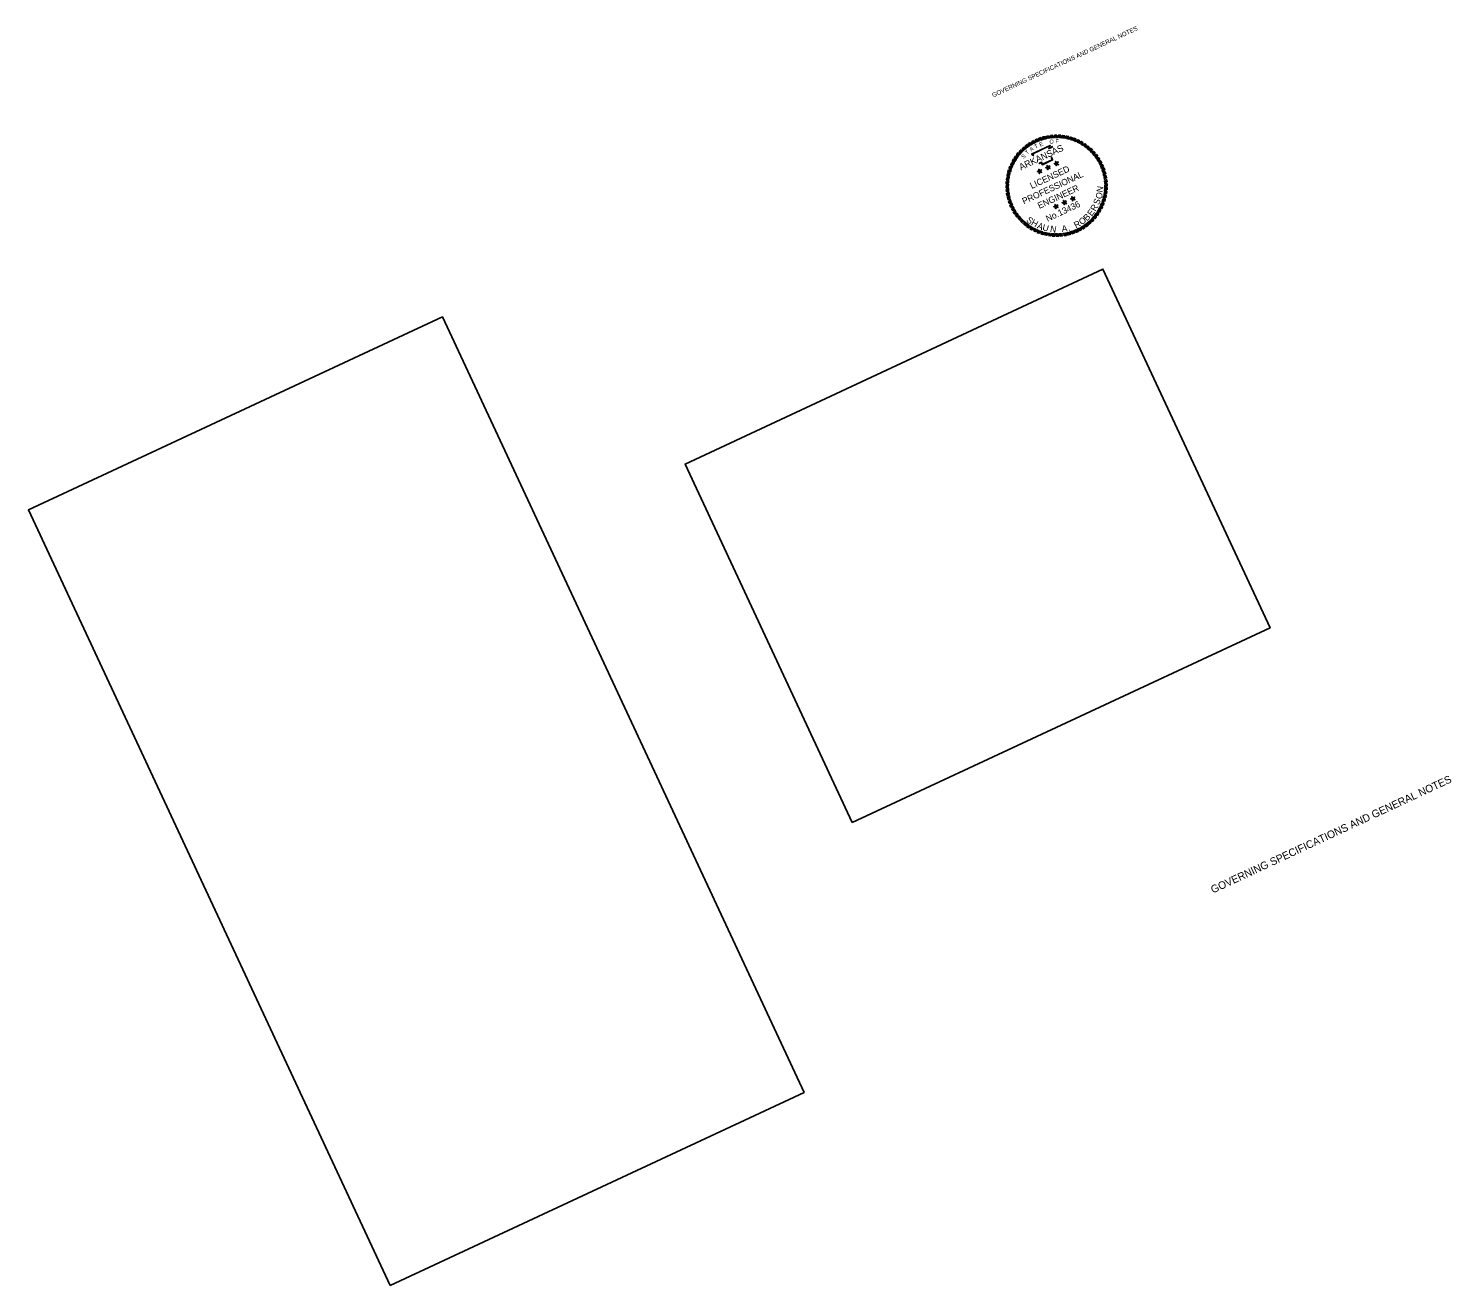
# Model space of a CAD drawing. Extents: x 757035 to 763666, y 1656342 to 1660766.
# Drawn here: x 760309 to 763666, y 1657801 to 1660766 of the extents above; entities that cross this region are included whole.
import ezdxf

# ---------------------------------------------------------------- set-up
doc = ezdxf.new("R2010")
doc.units = 0
for name, color, linetype in [('1', 7, 'Continuous'), ('60', 7, 'Continuous'), ('G-ANNO-SYMB', 7, 'Continuous')]:
    doc.layers.add(name, color=color, linetype=linetype)

msp = doc.modelspace()

# ---------------------------------------------------------------- linework, layer by layer
at = {"layer": '1'}
for points in [[(762252.5, 1658893), (763238.4, 1659352.7), (762844, 1660198.5), (761858.1, 1659738.8)], [(761162.2, 1657801), (762139, 1658256.5), (761285.8, 1660086.1), (760309, 1659630.7)]]:
    msp.add_lwpolyline(points, close=True, dxfattribs=at)
at = {"layer": 'G-ANNO-SYMB'}
for points in [[(762698.5, 1660509), (762693.7, 1660507.3), (762688.9, 1660499.5), (762694, 1660501.6)], [(762707.6, 1660511.5), (762702.6, 1660510.2), (762697.2, 1660502.8), (762702.5, 1660504.5)], [(762716.8, 1660513.2), (762711.7, 1660512.4), (762705.8, 1660505.4), (762711.2, 1660506.7)], [(762726.1, 1660514.3), (762721, 1660513.8), (762714.5, 1660507.3), (762720, 1660508.2)], [(762735.4, 1660514.6), (762730.3, 1660514.5), (762723.4, 1660508.6), (762728.9, 1660509)], [(762744.8, 1660514.2), (762739.7, 1660514.5), (762732.3, 1660509.1), (762737.8, 1660509.1)], [(762754.1, 1660513), (762749, 1660513.7), (762741.2, 1660509), (762746.7, 1660508.5)], [(762763.3, 1660511.1), (762758.3, 1660512.2), (762750.1, 1660508.1), (762755.6, 1660507.2)], [(762772.3, 1660508.5), (762767.4, 1660510), (762758.9, 1660506.5), (762764.3, 1660505.2)], [(762781, 1660505.2), (762776.3, 1660507.1), (762767.6, 1660504.3), (762772.8, 1660502.6)], [(762644.4, 1660473.3), (762641.2, 1660469.4), (762641.2, 1660460.2), (762644.4, 1660464.7)], [(762650.9, 1660480.2), (762647.3, 1660476.5), (762646.6, 1660467.4), (762650.2, 1660471.6)], [(762657.8, 1660486.5), (762653.9, 1660483.1), (762652.5, 1660474.1), (762656.4, 1660478)], [(762665.2, 1660492.2), (762661.1, 1660489.2), (762658.9, 1660480.3), (762663.2, 1660483.9)], [(762673, 1660497.4), (762668.7, 1660494.7), (762665.8, 1660486), (762670.3, 1660489.2)], [(762681.2, 1660501.9), (762676.7, 1660499.5), (762673.2, 1660491.1), (762677.9, 1660494)], [(762689.7, 1660505.8), (762685, 1660503.8), (762680.9, 1660495.6), (762685.8, 1660498.1)], [(762789.5, 1660501.2), (762784.9, 1660503.5), (762776, 1660501.4), (762781.1, 1660499.2)], [(762797.7, 1660496.6), (762793.3, 1660499.2), (762784.2, 1660497.8), (762789.2, 1660495.3)], [(762805.4, 1660491.4), (762801.2, 1660494.3), (762792.1, 1660493.6), (762796.8, 1660490.7)], [(762812.7, 1660485.5), (762808.8, 1660488.8), (762799.7, 1660488.8), (762804.1, 1660485.5)], [(762819.6, 1660479.1), (762815.9, 1660482.7), (762806.8, 1660483.4), (762811, 1660479.8)], [(762825.9, 1660472.2), (762822.5, 1660476), (762813.5, 1660477.5), (762817.4, 1660473.5)], [(762624.7, 1660441.6), (762622.8, 1660436.9), (762625.7, 1660428.2), (762627.4, 1660433.4)], [(762628.7, 1660450.1), (762626.5, 1660445.5), (762628.6, 1660436.6), (762630.7, 1660441.7)], [(762633.3, 1660458.3), (762630.7, 1660453.8), (762632.2, 1660444.8), (762634.7, 1660449.7)], [(762638.6, 1660466), (762635.6, 1660461.8), (762636.4, 1660452.7), (762639.3, 1660457.4)], [(762714.6, 1660438.3), (762715, 1660440.4), (762712.3, 1660443.3), (762712.8, 1660439.3)], [(762714.6, 1660438.3), (762716.7, 1660438.6), (762718.6, 1660442.1), (762715, 1660440.4)], [(762734.4, 1660447.6), (762732.6, 1660448.6), (762729, 1660446.9), (762732.9, 1660446.1)], [(762734.4, 1660447.6), (762734.8, 1660449.6), (762732.1, 1660452.5), (762732.6, 1660448.6)], [(762734.4, 1660447.6), (762732.9, 1660446.1), (762733.3, 1660442.2), (762735.3, 1660445.7)], [(762734.4, 1660447.6), (762736.4, 1660447.8), (762738.4, 1660451.3), (762734.8, 1660449.6)], [(762734.4, 1660447.6), (762735.3, 1660445.7), (762739.2, 1660444.9), (762736.4, 1660447.8)], [(762831.7, 1660464.8), (762828.6, 1660468.9), (762819.7, 1660471), (762823.3, 1660466.8)], [(762836.8, 1660457), (762834.1, 1660461.3), (762825.4, 1660464.1), (762828.6, 1660459.6)], [(762841.3, 1660448.8), (762838.9, 1660453.3), (762830.5, 1660456.8), (762833.4, 1660452.1)], [(762845.2, 1660440.2), (762843.2, 1660444.9), (762835, 1660449.1), (762837.5, 1660444.2)], [(762848.4, 1660431.4), (762846.7, 1660436.3), (762838.9, 1660441.1), (762841, 1660435.9)], [(762617, 1660414.7), (762616.2, 1660409.6), (762621, 1660401.8), (762621.5, 1660407.3)], [(762618.8, 1660423.9), (762617.7, 1660418.9), (762621.9, 1660410.7), (762622.8, 1660416.2)], [(762621.4, 1660432.9), (762619.9, 1660428), (762623.4, 1660419.5), (762624.7, 1660424.9)], [(762694.8, 1660429.1), (762693, 1660430.1), (762689.4, 1660428.5), (762693.3, 1660427.7)], [(762694.8, 1660429.1), (762695.2, 1660431.2), (762692.5, 1660434.1), (762693, 1660430.1)], [(762694.8, 1660429.1), (762693.3, 1660427.7), (762693.8, 1660423.8), (762695.7, 1660427.2)], [(762694.8, 1660429.1), (762696.9, 1660429.4), (762698.8, 1660432.8), (762695.2, 1660431.2)], [(762694.8, 1660429.1), (762695.7, 1660427.2), (762699.6, 1660426.5), (762696.9, 1660429.4)], [(762714.6, 1660438.3), (762712.8, 1660439.3), (762709.2, 1660437.7), (762713.1, 1660436.9)], [(762714.6, 1660438.3), (762713.1, 1660436.9), (762713.6, 1660433), (762715.5, 1660436.4)], [(762714.6, 1660438.3), (762715.5, 1660436.4), (762719.4, 1660435.7), (762716.7, 1660438.6)], [(762850.9, 1660422.4), (762849.6, 1660427.4), (762842.2, 1660432.7), (762843.9, 1660427.5)], [(762852.7, 1660413.2), (762851.8, 1660418.3), (762844.8, 1660424.2), (762846.1, 1660418.8)], [(762853.7, 1660403.9), (762853.2, 1660409), (762846.7, 1660415.5), (762847.6, 1660410)], [(762854, 1660394.5), (762853.9, 1660399.7), (762848, 1660406.6), (762848.4, 1660401.1)], [(762615.4, 1660396), (762615.4, 1660390.9), (762621.4, 1660383.9), (762621, 1660389.5)], [(762615.8, 1660405.4), (762615.5, 1660400.3), (762620.8, 1660392.9), (762620.9, 1660398.4)], [(762615.7, 1660386.7), (762616.2, 1660381.6), (762622.6, 1660375.1), (762621.8, 1660380.6)], [(762616.7, 1660377.4), (762617.6, 1660372.3), (762624.6, 1660366.4), (762623.3, 1660371.8)], [(762850.5, 1660366.7), (762851.7, 1660371.7), (762847.5, 1660379.8), (762846.6, 1660374.4)], [(762852.4, 1660375.9), (762853.1, 1660380.9), (762848.4, 1660388.7), (762847.9, 1660383.2)], [(762853.6, 1660385.2), (762853.9, 1660390.3), (762848.5, 1660397.7), (762848.5, 1660392.1)], [(762618.5, 1660368.2), (762619.8, 1660363.2), (762627.2, 1660357.8), (762625.5, 1660363.1)], [(762621, 1660359.1), (762622.6, 1660354.3), (762630.4, 1660349.5), (762628.3, 1660354.6)], [(762624.2, 1660350.3), (762626.2, 1660345.6), (762634.3, 1660341.5), (762631.8, 1660346.4)], [(762628, 1660341.8), (762630.4, 1660337.2), (762638.9, 1660333.7), (762636, 1660338.5)], [(762733.4, 1660346.3), (762731.6, 1660347.3), (762728, 1660345.6), (762731.9, 1660344.9)], [(762733.4, 1660346.3), (762733.8, 1660348.4), (762731.1, 1660351.3), (762731.6, 1660347.3)], [(762733.4, 1660346.3), (762731.9, 1660344.9), (762732.4, 1660341), (762734.3, 1660344.4)], [(762733.4, 1660346.3), (762735.5, 1660346.6), (762737.4, 1660350), (762733.8, 1660348.4)], [(762733.4, 1660346.3), (762734.3, 1660344.4), (762738.2, 1660343.7), (762735.5, 1660346.6)], [(762753.2, 1660355.5), (762751.4, 1660356.5), (762747.8, 1660354.9), (762751.7, 1660354.1)], [(762753.2, 1660355.5), (762753.6, 1660357.6), (762750.9, 1660360.5), (762751.4, 1660356.5)], [(762753.2, 1660355.5), (762751.7, 1660354.1), (762752.2, 1660350.2), (762754.1, 1660353.6)], [(762753.2, 1660355.5), (762755.3, 1660355.8), (762757.2, 1660359.3), (762753.6, 1660357.6)], [(762753.2, 1660355.5), (762754.1, 1660353.6), (762758, 1660352.9), (762755.3, 1660355.8)], [(762773, 1660364.8), (762771.2, 1660365.8), (762767.6, 1660364.1), (762771.5, 1660363.3)], [(762773, 1660364.8), (762773.4, 1660366.8), (762770.7, 1660369.7), (762771.2, 1660365.8)], [(762773, 1660364.8), (762771.5, 1660363.3), (762772, 1660359.4), (762773.9, 1660362.9)], [(762773, 1660364.8), (762775.1, 1660365), (762777, 1660368.5), (762773.4, 1660366.8)], [(762773, 1660364.8), (762773.9, 1660362.9), (762777.8, 1660362.1), (762775.1, 1660365)], [(762836, 1660332.3), (762838.6, 1660336.7), (762837.2, 1660345.7), (762834.7, 1660340.8)], [(762840.7, 1660340.4), (762842.9, 1660345), (762840.8, 1660353.9), (762838.6, 1660348.8)], [(762844.6, 1660348.9), (762846.5, 1660353.7), (762843.7, 1660362.4), (762842, 1660357.1)], [(762847.9, 1660357.7), (762849.4, 1660362.6), (762845.9, 1660371), (762844.6, 1660365.7)], [(762632.6, 1660333.6), (762635.3, 1660329.2), (762644, 1660326.4), (762640.8, 1660330.9)], [(762637.7, 1660325.8), (762640.8, 1660321.6), (762649.7, 1660319.5), (762646.1, 1660323.7)], [(762643.5, 1660318.4), (762646.9, 1660314.5), (762655.9, 1660313.1), (762652, 1660317)], [(762649.8, 1660311.4), (762653.5, 1660307.9), (762662.6, 1660307.1), (762658.4, 1660310.8)], [(762804.2, 1660298.3), (762808.3, 1660301.4), (762810.4, 1660310.3), (762806.2, 1660306.7)], [(762811.6, 1660304.1), (762815.5, 1660307.4), (762816.9, 1660316.5), (762813, 1660312.6)], [(762818.5, 1660310.4), (762822.1, 1660314.1), (762822.8, 1660323.2), (762819.2, 1660319)], [(762824.9, 1660317.2), (762828.2, 1660321.2), (762828.2, 1660330.3), (762824.9, 1660325.8)], [(762830.8, 1660324.5), (762833.7, 1660328.7), (762833, 1660337.8), (762830.1, 1660333.1)], [(762656.6, 1660305), (762660.6, 1660301.8), (762669.7, 1660301.8), (762665.2, 1660305)], [(762663.9, 1660299.2), (762668.1, 1660296.2), (762677.3, 1660297), (762672.5, 1660299.9)], [(762671.7, 1660293.9), (762676.1, 1660291.3), (762685.1, 1660292.8), (762680.2, 1660295.3)], [(762679.8, 1660289.3), (762684.5, 1660287), (762693.3, 1660289.2), (762688.2, 1660291.3)], [(762688.3, 1660285.3), (762693.1, 1660283.4), (762701.8, 1660286.3), (762696.5, 1660288)], [(762697.1, 1660282), (762702, 1660280.5), (762710.5, 1660284), (762705.1, 1660285.3)], [(762706.1, 1660279.4), (762711.1, 1660278.3), (762719.3, 1660282.5), (762713.8, 1660283.3)], [(762715.3, 1660277.5), (762720.4, 1660276.8), (762728.2, 1660281.6), (762722.6, 1660282.1)], [(762724.6, 1660276.4), (762729.7, 1660276.1), (762737.1, 1660281.4), (762731.5, 1660281.5)], [(762733.9, 1660276), (762739.1, 1660276), (762746, 1660282), (762740.5, 1660281.6)], [(762743.3, 1660276.3), (762748.4, 1660276.7), (762754.9, 1660283.2), (762749.4, 1660282.4)], [(762752.6, 1660277.3), (762757.7, 1660278.2), (762763.6, 1660285.1), (762758.2, 1660283.9)], [(762761.8, 1660279.1), (762766.8, 1660280.4), (762772.2, 1660287.8), (762766.9, 1660286.1)], [(762770.8, 1660281.6), (762775.7, 1660283.2), (762780.5, 1660291), (762775.3, 1660288.9)], [(762779.6, 1660284.8), (762784.4, 1660286.8), (762788.5, 1660294.9), (762783.6, 1660292.4)], [(762788.2, 1660288.6), (762792.7, 1660291), (762796.2, 1660299.5), (762791.5, 1660296.6)], [(762796.4, 1660293.1), (762800.7, 1660295.9), (762803.5, 1660304.6), (762799.1, 1660301.3)]]:
    msp.add_lwpolyline(points, close=True, dxfattribs=at)
for points in [[(762680.8, 1660465.7), (762675.7, 1660470), (762719.3, 1660490.3), (762717.8, 1660484.1), (762720.7, 1660485.5), (762723.2, 1660486.7), (762725.8, 1660487.5)], [(762681.3, 1660466.3), (762677.1, 1660469.8), (762718.2, 1660489), (762716.7, 1660482.7), (762721.1, 1660484.8), (762723.5, 1660486), (762726, 1660486.8)], [(762723.5, 1660463.4), (762723, 1660462.4), (762723.2, 1660461.4), (762724, 1660459), (762725.4, 1660456), (762701.1, 1660444.6), (762699.2, 1660448.7), (762698.8, 1660449.6), (762697.6, 1660449.5), (762694.2, 1660447.8), (762693.1, 1660448.5)], [(762722.8, 1660463.7), (762722.3, 1660462.5), (762722.5, 1660461.2), (762723.3, 1660458.7), (762724.4, 1660456.4), (762701.5, 1660445.7), (762699.9, 1660449), (762699.2, 1660450.5), (762697.4, 1660450.2), (762694.2, 1660448.7), (762693.5, 1660449.1)]]:
    msp.add_lwpolyline(points, dxfattribs=at)

# ---------------------------------------------------------------- texts
at = {"layer": '1'}
msp.add_text('GOVERNING SPECIFICATIONS AND GENERAL NOTES', height=10.552, rotation=25, dxfattribs=at).set_placement((762585.3, 1660603.3))
at = {"layer": '60'}
msp.add_text('GOVERNING SPECIFICATIONS AND GENERAL NOTES', height=18, rotation=25, dxfattribs=at).set_placement((763103.6, 1658725.6))
at = {"layer": 'G-ANNO-SYMB'}
for s, height, rotation, p in [('ARKANSAS', 15.49, 25, (762650.4, 1660431.2)), ('T', 9.49, 41.9015, (762665.4, 1660468)), ('A', 9.49, 33.6788, (762674.5, 1660475.6)), ('T', 9.49, 26.4789, (762684.8, 1660482.5)), ('E', 9.49, 21.672, (762696, 1660487.3)), ('O', 9.49, 6.2218, (762718.2, 1660494.1)), ('F', 9.49, 0.3628, (762732, 1660495)), ('S', 9.49, 44.7726, (762656.7, 1660458)), ('LICENSED', 15, 25, (762676.1, 1660387.4)), ('PROFESSIONAL', 15, 25, (762657.6, 1660351)), ('ENGINEER', 15, 25, (762694.1, 1660340.4)), ('O', 15, 69.7757, (762839.6, 1660362.1)), ('N', 15, 81.1007, (762843.3, 1660378.8)), ('No.13436', 14.94, 25, (762713.5, 1660310)), ('E', 15, 52.8315, (762817.6, 1660322.3)), ('R', 15, 60.6597, (762826.3, 1660333.7)), ('S', 15, 68.4878, (762834.4, 1660348.8)), ('S', 15, 323.1636, (762661.9, 1660311.5)), ('H', 15, 330.619, (762673.1, 1660303.7)), ('A', 15, 338.4472, (762687.5, 1660295.3)), ('R', 15, 28.2287, (762780.4, 1660294.4)), ('O', 15, 36.4296, (762793.9, 1660301.8)), ('B', 15, 43.885, (762806.1, 1660311)), ('U', 15, 345.9026, (762700.1, 1660290.4)), ('N', 15, 349.9326, (762718.5, 1660286.7)), ('A', 15, 8.0991, (762747.7, 1660286.1)), ('.', 15, 16.3, (762762.9, 1660288.3))]:
    msp.add_text(s, height=height, rotation=rotation, dxfattribs=at).set_placement(p)

doc.saveas('drawing.dxf')
